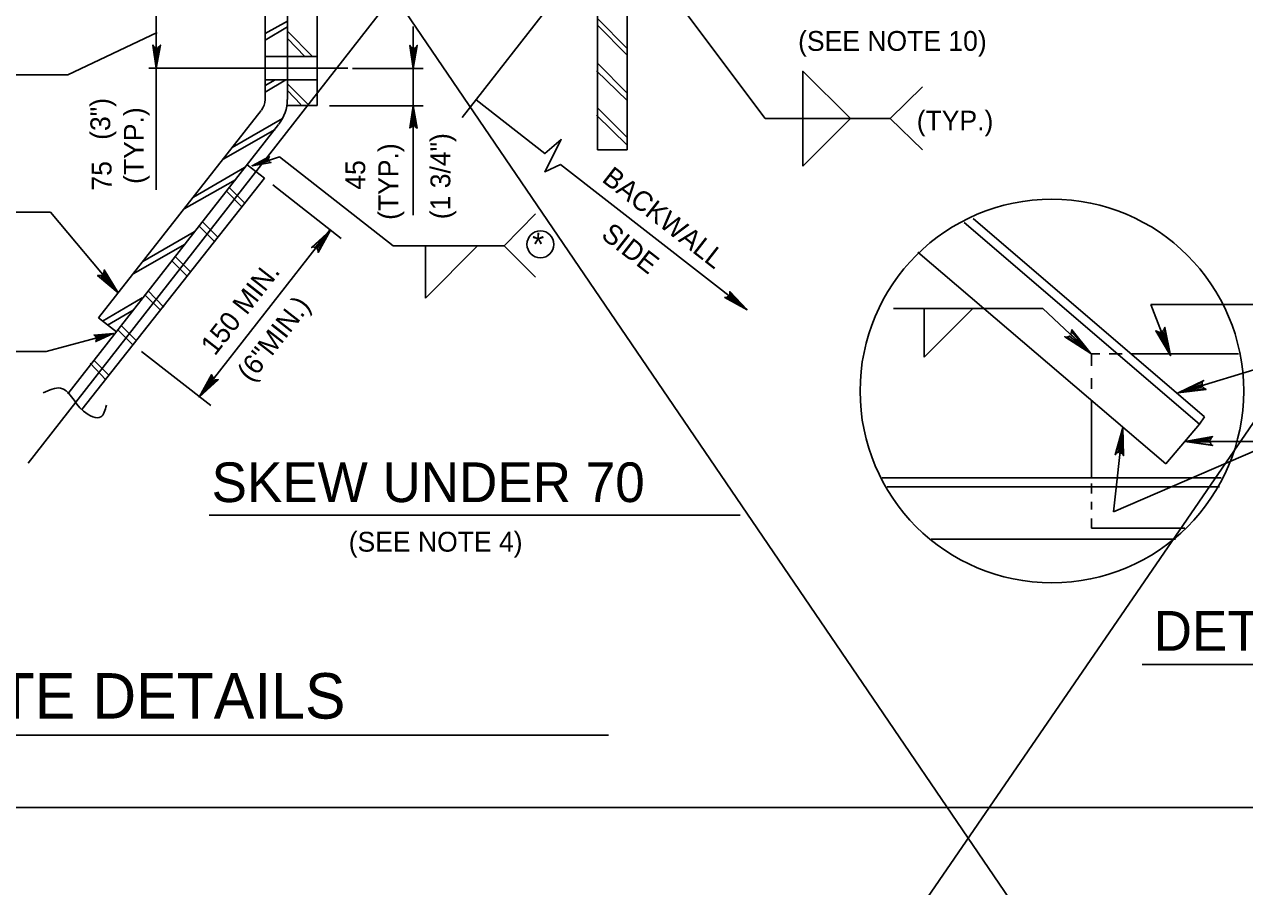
# Model space of a CAD drawing. Extents: x 634656 to 641360, y 298715 to 301183.
# Drawn here: x 640490.1 to 640674.7, y 299423.1 to 299553.5 of the extents above; entities that cross this region are included whole.
import ezdxf

# ---------------------------------------------------------------- set-up
doc = ezdxf.new("R2010")
doc.units = 0
for name, color, linetype in [('1', 7, 'Continuous'), ('2', 7, 'Continuous'), ('40', 7, 'Continuous')]:
    doc.layers.add(name, color=color, linetype=linetype)

msp = doc.modelspace()

# ---------------------------------------------------------------- linework, layer by layer
at = {"layer": '1'}
for p, q in [((641102.54, 300114.62), (640153.96, 298732.63)), ((640203.02, 300061.47), (641094.36, 298753.08))]:
    msp.add_line(p, q, dxfattribs=at)
at = {"layer": '2'}
for p, q in [((640556.33, 299539.43), (640601.68, 299597.52)), ((640529.93, 299542.14), (640529.93, 299566.89)), ((640534.43, 299541.27), (640534.43, 299566.89)), ((640576.8, 299566.77), (640576.8, 299534.52)), ((640581.3, 299566.77), (640581.3, 299534.52)), ((640602.19, 299539.3), (640581.9, 299566.34)), ((640490.68, 299487.14), (640551.4, 299564.88)), ((640526.55, 299542.14), (640526.55, 299563.27)), ((640510.05, 299557.64), (640510.05, 299546.89)), ((640526.55, 299552.14), (640529.93, 299554.02)), ((640526.55, 299551.14), (640529.93, 299553.14)), ((640548.93, 299553.21), (640548.93, 299546.84)), ((640581.3, 299549.89), (640576.8, 299554.39)), ((640581.3, 299548.89), (640576.8, 299553.39)), ((640496.68, 299545.89), (640510.18, 299552.27)), ((640529.93, 299552.52), (640533.68, 299548.64)), ((640529.93, 299551.39), (640532.55, 299548.64)), ((640534.43, 299548.64), (640526.55, 299548.64)), ((640581.3, 299543.14), (640576.8, 299547.64)), ((640496.68, 299545.89), (640446.3, 299545.89)), ((640524.8, 299546.89), (640508.93, 299546.89)), ((640510.05, 299528.51), (640510.05, 299546.89)), ((640539.05, 299546.89), (640524.8, 299546.89)), ((640550.43, 299546.84), (640539.77, 299546.84)), ((640548.93, 299524.68), (640548.93, 299546.84)), ((640581.3, 299542.02), (640576.68, 299546.52)), ((640534.43, 299545.14), (640526.55, 299545.14)), ((640526.55, 299544.27), (640528.05, 299545.14)), ((640526.55, 299543.27), (640529.68, 299545.14)), ((640529.93, 299544.52), (640533.05, 299541.39)), ((640529.93, 299543.52), (640531.93, 299541.39)), ((640558.46, 299542.1), (640568.83, 299533.97)), ((640525.93, 299540.52), (640501.3, 299509.14)), ((640529.93, 299541.27), (640534.43, 299541.27)), ((640550.43, 299541.21), (640536.26, 299541.21)), ((640581.3, 299535.27), (640576.68, 299539.77)), ((640581.3, 299536.39), (640576.8, 299540.89)), ((640528.55, 299538.39), (640496.68, 299497.64)), ((640521.55, 299534.89), (640529.18, 299539.27)), ((640621.13, 299539.3), (640602.19, 299539.3)), ((640607.88, 299539.3), (640607.88, 299532.05)), ((640607.88, 299532.05), (640615.13, 299539.3)), ((640520.18, 299533.14), (640528.05, 299537.64)), ((640581.3, 299534.52), (640576.8, 299534.52)), ((640528.7, 299533.5), (640524.55, 299532.14)), ((640528.7, 299533.5), (640545.93, 299520.01)), ((640571.21, 299532.35), (640599.46, 299510.35)), ((640523.43, 299531.89), (640515.68, 299527.39)), ((640526.43, 299530.27), (640523.8, 299532.27)), ((640498.8, 299495.27), (640526.43, 299530.27)), ((640522.05, 299530.02), (640514.3, 299525.64)), ((640521.18, 299528.77), (640523.43, 299526.52)), ((640527.68, 299529.27), (640538.05, 299521.14)), ((640520.68, 299528.27), (640523.05, 299525.89)), ((640494.05, 299525.14), (640449.3, 299525.14)), ((640494.05, 299525.14), (640504.3, 299512.89)), ((640517.05, 299523.64), (640519.43, 299521.27)), ((640667.92, 299493.05), (640632.3, 299523.55)), ((640633.67, 299524.17), (640668.67, 299494.17)), ((640515.8, 299522.14), (640508.05, 299517.64)), ((640516.55, 299523.02), (640518.93, 299520.64)), ((640536.43, 299522.52), (640516.55, 299497.14)), ((640514.43, 299520.27), (640506.55, 299515.77)), ((640562.69, 299520.01), (640545.93, 299520.01)), ((640550.82, 299520.01), (640550.82, 299512.13)), ((640550.82, 299512.13), (640558.69, 299520.01)), ((640512.43, 299517.77), (640514.8, 299515.39)), ((640512.93, 299518.39), (640515.3, 299516.02)), ((640625.3, 299519.05), (640662.8, 299487.05)), ((640507.93, 299512.14), (640501.93, 299508.64)), ((640508.3, 299512.64), (640510.68, 299510.27)), ((640508.8, 299513.27), (640511.18, 299510.77)), ((640506.55, 299510.27), (640502.68, 299508.02)), ((640621.61, 299510.56), (640644.23, 299510.56)), ((640626.26, 299510.56), (640626.26, 299503.19)), ((640626.26, 299503.19), (640633.62, 299510.56)), ((640644.23, 299510.56), (640651.55, 299503.64)), ((640660.57, 299511.17), (640663.55, 299503.42)), ((640706.28, 299511.17), (640660.57, 299511.17)), ((640504.05, 299507.02), (640501.3, 299509.14)), ((640493.42, 299504.05), (640503.55, 299506.77)), ((640504.18, 299507.39), (640506.55, 299505.02)), ((640504.68, 299508.02), (640507.05, 299505.64)), ((640475.42, 299504.05), (640493.42, 299504.05)), ((640500.55, 299502.77), (640502.93, 299500.39)), ((640507.8, 299504.02), (640518.3, 299495.89)), ((640651.55, 299503.67), (640651.55, 299501.88)), ((640652.85, 299503.67), (640651.55, 299503.67)), ((640656.2, 299503.67), (640654.27, 299503.67)), ((640673.8, 299503.67), (640657.59, 299503.67)), ((640500.05, 299502.27), (640502.43, 299499.77)), ((640680.42, 299502.55), (640664.67, 299497.8)), ((640651.55, 299500.01), (640651.55, 299498.4)), ((640651.55, 299496.65), (640651.55, 299484.92)), ((640667.92, 299493.05), (640668.67, 299494.17)), ((640654.92, 299479.8), (640656.3, 299492.55)), ((640662.8, 299487.05), (640667.92, 299493.05)), ((640654.92, 299479.8), (640680.34, 299490.79)), ((640665.67, 299490.42), (640685.22, 299490.42)), ((640667.17, 299490.42), (640695.8, 299490.42)), ((640671.17, 299484.92), (640619.92, 299484.92)), ((640670.92, 299483.55), (640620.67, 299483.55)), ((640651.55, 299484.05), (640651.55, 299482.55)), ((640651.55, 299481.3), (640651.55, 299480.13)), ((640518.05, 299479.26), (640598.43, 299479.26)), ((640651.55, 299478.8), (640651.55, 299477.3)), ((640665.67, 299477.3), (640651.55, 299477.3)), ((640664.3, 299475.67), (640627.3, 299475.67)), ((640659.24, 299456.67), (640708.36, 299456.67)), ((640342.23, 299446.01), (640578.48, 299446.01)), ((641029.86, 299435.08), (640243.86, 299435.08))]:
    msp.add_line(p, q, dxfattribs=at)
for points in [[(640510.43, 299550.14), (640510.3, 299550.02), (640510.05, 299546.89), (640510.43, 299550.14), (640510.68, 299550.39), (640510.05, 299546.89), (640509.93, 299550.02), (640509.68, 299550.14), (640510.05, 299546.89), (640509.55, 299550.39), (640509.68, 299550.14)], [(640549.43, 299550.09), (640549.18, 299549.96), (640548.93, 299546.84), (640549.43, 299550.09), (640549.56, 299550.34), (640548.93, 299546.84), (640548.81, 299549.96), (640548.56, 299550.09), (640548.93, 299546.84), (640548.43, 299550.34), (640548.56, 299550.09)], [(640607.88, 299539.3), (640607.88, 299546.42), (640615.13, 299539.3), (640607.88, 299539.3)], [(640626, 299544.05), (640621.13, 299539.3), (640626, 299534.55)], [(640558.46, 299542.1), (640568.83, 299533.97), (640571.33, 299536.1), (640568.83, 299531.22), (640571.21, 299532.35)], [(640548.56, 299537.96), (640548.81, 299538.09), (640548.93, 299541.21), (640548.56, 299537.96), (640548.43, 299537.84), (640548.93, 299541.21), (640549.18, 299538.09), (640549.31, 299537.96), (640548.93, 299541.21), (640549.56, 299537.84), (640549.31, 299537.96)], [(640527.3, 299532.64), (640527.05, 299532.89), (640524.55, 299532.14), (640527.3, 299532.64), (640527.43, 299532.64), (640524.55, 299532.14), (640527.05, 299533.14), (640527.05, 299533.27), (640524.55, 299532.14), (640527.18, 299533.52), (640527.05, 299533.27)], [(640567.44, 299524.88), (640562.69, 299520.01), (640567.44, 299515.26)], [(640533.8, 299519.89), (640534.05, 299519.77), (640536.43, 299522.39), (640533.8, 299519.89), (640533.55, 299519.77), (640536.43, 299522.39), (640534.43, 299519.64), (640534.55, 299519.27), (640536.43, 299522.39), (640534.55, 299519.02), (640534.55, 299519.27)], [(640502.18, 299516.14), (640502.05, 299515.77), (640504.3, 299512.89), (640502.18, 299516.14), (640502.18, 299516.39), (640504.3, 299512.89), (640501.8, 299515.52), (640501.55, 299515.52), (640504.3, 299512.89), (640501.18, 299515.52), (640501.55, 299515.52)], [(640596.83, 299512.85), (640596.83, 299512.6), (640599.46, 299510.35), (640596.83, 299512.85), (640596.83, 299513.1), (640599.46, 299510.35), (640596.58, 299512.35), (640596.33, 299512.22), (640599.46, 299510.35), (640596.08, 299512.22), (640596.33, 299512.22)], [(640500.8, 299506.42), (640500.98, 299506.21), (640503.55, 299506.77), (640500.8, 299506.42), (640500.65, 299506.51), (640503.55, 299506.77), (640501.05, 299505.97), (640500.99, 299505.69), (640503.55, 299506.77), (640500.91, 299505.54), (640500.99, 299505.69)], [(640647.91, 299506.19), (640648.26, 299506.38), (640651.47, 299503.73), (640647.91, 299506.19), (640647.52, 299506.26), (640651.47, 299503.73), (640648.47, 299506.66), (640648.53, 299507.05), (640651.47, 299503.73), (640648.62, 299507.32), (640648.53, 299507.05)], [(640662.55, 299507.42), (640662.3, 299507.17), (640663.55, 299503.42), (640662.55, 299507.42), (640662.67, 299507.67), (640663.55, 299503.42), (640661.92, 299506.92), (640661.55, 299507.05), (640663.55, 299503.42), (640661.3, 299507.17), (640661.55, 299507.05)], [(640519.18, 299499.77), (640518.93, 299499.77), (640516.55, 299497.14), (640519.18, 299499.77), (640519.43, 299499.77), (640516.55, 299497.14), (640518.68, 299500.02), (640518.55, 299500.27), (640516.55, 299497.14), (640518.43, 299500.52), (640518.55, 299500.27)], [(640668.3, 299499.42), (640668.3, 299499.05), (640664.67, 299497.8), (640668.3, 299499.42), (640668.55, 299499.67), (640664.67, 299497.8), (640668.42, 299498.67), (640668.67, 299498.42), (640664.67, 299497.8), (640668.92, 299498.3), (640668.67, 299498.42)], [(640656.3, 299488.55), (640656.05, 299488.67), (640656.3, 299492.55), (640656.3, 299488.55), (640656.42, 299488.3), (640656.3, 299492.55), (640655.67, 299488.8), (640655.3, 299488.67), (640656.3, 299492.55), (640655.17, 299488.42), (640655.3, 299488.67)], [(640669.67, 299490.92), (640669.55, 299490.67), (640665.67, 299490.42), (640669.67, 299490.92), (640669.92, 299491.17), (640665.67, 299490.42), (640669.55, 299490.3), (640669.67, 299489.92), (640665.67, 299490.42), (640669.92, 299489.8), (640669.67, 299489.92)]]:
    msp.add_lwpolyline(points, dxfattribs=at)
for centre, radius in [((640645.58, 299498.06), 29.02), ((640568.19, 299520.25), 2.04)]:
    msp.add_circle(centre, radius, dxfattribs=at)
for radius in [2.63, 6]:
    msp.add_arc((640523.89, 299542.15), radius, 321.9254, 360, dxfattribs=at)
msp.add_spline([(640492.94, 299497.77), (640495.55, 299498.51), (640499.05, 299495.02), (640501.68, 299494.14), (640502.51, 299495.9)], degree=3, dxfattribs=at)

# ---------------------------------------------------------------- texts
for s, height, p in [('(SEE NOTE 10)', 3, (640607.18, 299549.52)), ('(TYP.)', 3, (640625.13, 299537.47)), ('*', 3.5, (640566.94, 299518.51)), ('SKEW UNDER 70', 6, (640518.43, 299481.26)), ('(SEE NOTE 4)', 3, (640539.18, 299473.76)), ('DETAIL D', 6, (640660.99, 299458.78)), ('DIAPHRAGM CONNECTION PLATE DETAILS', 6.8753, (640346.1, 299448.51))]:
    msp.add_text(s, height=height, dxfattribs=at).set_placement(p)
for s, rotation, p in [('(TYP.)', 90, (640508.17, 299529.39)), ('(TYP.)', 90, (640546.67, 299523.95)), ('75', 90, (640503.29, 299528.38)), ('45', 90, (640541.67, 299528.51)), ('BACKWALL', 322, (640577.33, 299529.85)), ('SIDE', 322, (640577.21, 299521.35)), ('150 MIN.', 51.9975, (640518.92, 299503.26))]:
    msp.add_text(s, height=3, rotation=rotation, dxfattribs=at).set_placement(p)
at = {"layer": '40'}
for s, rotation, p in [('(3")', 90, (640503.09, 299536.06)), ('(1 3/4")', 90, (640554.55, 299524.05)), ('(6"MIN.)', 51.9975, (640524.43, 299499.25))]:
    msp.add_text(s, height=3, rotation=rotation, dxfattribs=at).set_placement(p)

doc.saveas('drawing.dxf')
